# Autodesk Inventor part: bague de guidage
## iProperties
Shininess: 64.0
Length Units: 11269
Angle Units: 11279
Time Units: 11290
Mass Units: 11283
Length Display Precision: 3
Angle Display Precision: 2
Compacted: True
Part Number: bague de guidage
Document SubType Name: Modeling
Created: 2005-01
Material: Par défaut
Designer: LEGERET Philippe
Density: 0.0
Volumn: 0.0
Area: 0.0
PropertySet Name: Model Information
Control State: 0
Master: False
Checked Out: False
Author: LEGERET Philippe
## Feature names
1. Extrusion1
2. Extrusion2
3. Extrusion3
4. Perçage1 [Hole]
5. Extrusion4
